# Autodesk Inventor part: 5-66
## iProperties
Company: HERDT-Verlag
Shininess: 64.0
Length Units: 11269
Angle Units: 11279
Time Units: 11290
Mass Units: 11283
Length Display Precision: 3
Angle Display Precision: 2
Compacted: True
Part Number: 5-66
Document SubType Name: Modeling
Created: 2006-01
Material: Standard
Designer: Eichenseer
Checked By: G. Lehmann
Engr Approved By: M. Grouls
Project: Inventor 11 - Grundkurs
Density: 0.0
Volumn: 0.0
Area: 0.0
PropertySet Name: Model Information
Control State: 0
Master: False
Checked Out: False
Author: P. Tropf
Subject: Inventor 10 - Grundkurs
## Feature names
1. Extrusion1
